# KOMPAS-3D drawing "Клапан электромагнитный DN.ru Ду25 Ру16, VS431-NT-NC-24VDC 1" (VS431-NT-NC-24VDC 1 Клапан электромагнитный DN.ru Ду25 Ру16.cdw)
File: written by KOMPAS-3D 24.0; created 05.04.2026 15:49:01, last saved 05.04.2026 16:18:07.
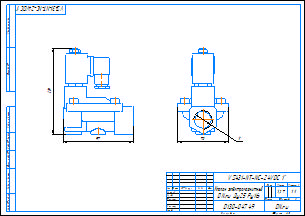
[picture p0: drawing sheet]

Document properties: c3d_UniqueCompID: ef56311e-7521-43dc-8291-0e6108b3d81d; Автор: artio; Класс точности: c; Знак неуказанной шероховатости: Шероховатость не задана; Рассекать на разрезах: Да; c3d_UniqueCompID: ef56311e-7521-43dc-8291-0e6108b3d81d; Автор: artio; Класс точности: c; Знак неуказанной шероховатости: Шероховатость не задана; Рассекать на разрезах: Да; Автор: artio; Форматы листов документа: A3; Полное имя файла: VS431-NT-NC-24VDC 1 Клапан электромагнитный DN.ru Ду25 Ру16.m3d; Масса: 1.267; Наименование: Клапан электромагнитный DN.ru Ду25 Ру16; Количество листов документа: 1; Примечание: D130-04749

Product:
- Body: Тело 1  | qty 1
    Масса: 1.729172
- Part/product: Клапан электромагнитный DN.ru Ду25 Ру16  | designation VS431-NT-NC-24VDC 1
    Масса: 1.267
    Раздел спецификации: Прочие изделия
    Примечание: D130-04749
    additional columns: ef56311e-7521-43dc-8291-0e6108b3d81d; artio; c; Шероховатость не задана; Да

Views: Вид 1, Спереди, Проекционный вид 2
Referenced files in C:\Users\artio\OneDrive\Рабочий стол\Клапан электромагнитный DN.ru\VS431\VS431-ET-NC\: VS431-ET-NC-24VDC 3-4 Клапан электромагнитный DN.ru Ду20 Ру16.m3d, VS431-ET-NC-24VDC 3-4 Клапан электромагнитный DN.ru Ду20 Ру16.cdw
Referenced files in C:\Users\artio\OneDrive\Рабочий стол\Клапан электромагнитный DN.ru\VS431\VS431-NT-NC\: VS431-NT-NC-24VDC 1 Клапан электромагнитный DN.ru Ду25 Ру16.m3d
Referenced files in C:\Users\artio\OneDrive\Рабочий стол\Клапан электромагнитный DN.ru\VS431\VS431-NT-NC\VS431-NT-NC-24VDC\Ду25\: VS431-NT-NC-24VDC 1 Клапан электромагнитный DN.ru Ду25 Ру16.m3d
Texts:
  VS431-NT-NC-24VDC 1
  Клапан электромагнитный
  DN.ru Ду25 Ру16
  VS431-NT-NC-24VDC 1"
  VS431-NT-NC-24VDC 1"-
  Клапан электромагнитный DN.ru Ду25 Ру16
  VS431-NT-NC-24VDC 1 Клапан электромагнитный DN.ru Ду25 Ру16
Dimensions and other numbers on the sheet: 0; 3; 2; 4; 70; 97; 119; 1:1; 1; 1,27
